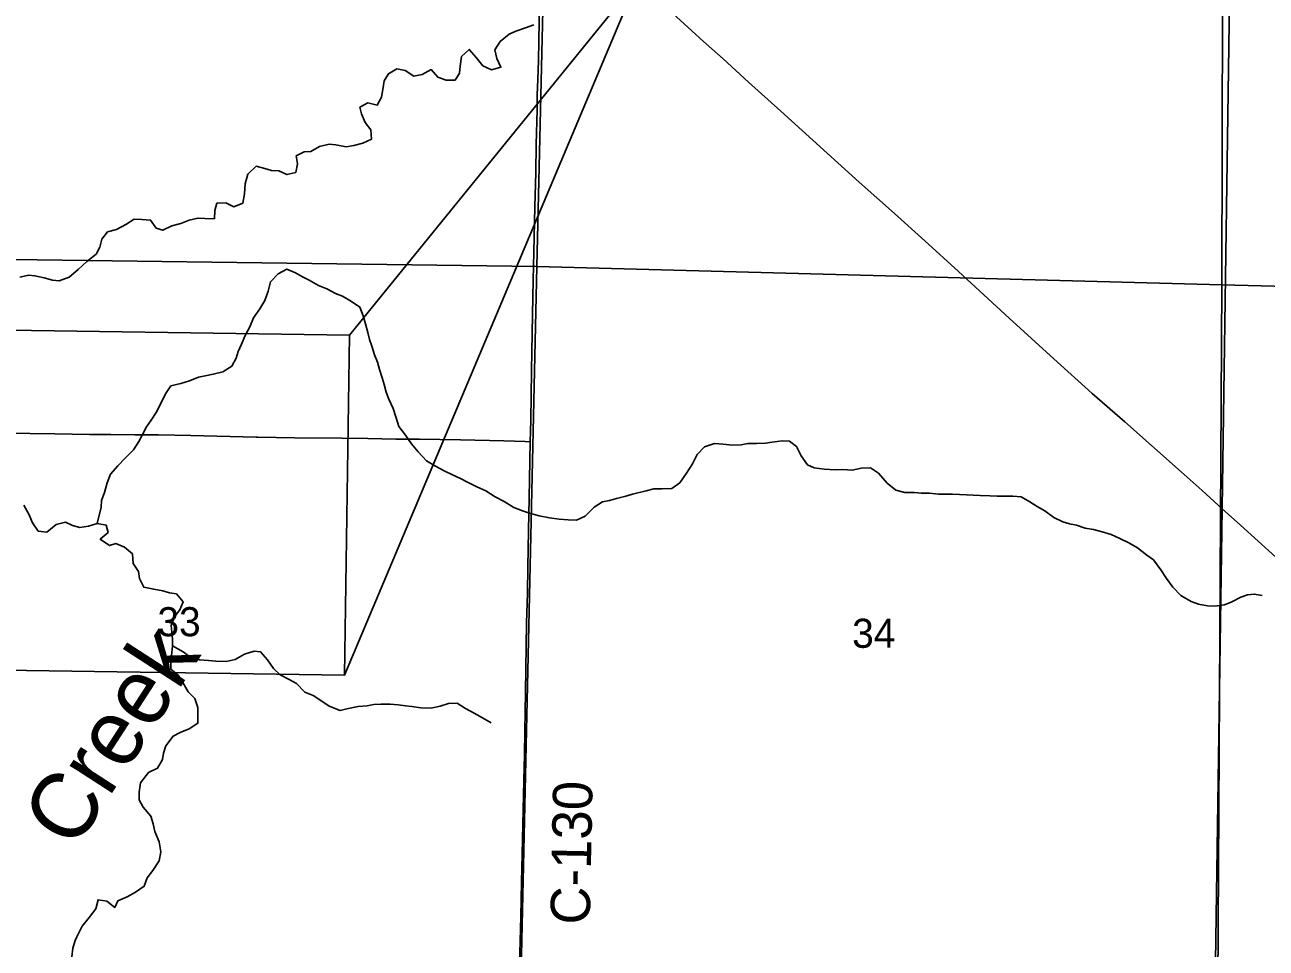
# Model space of a CAD drawing. Extents: x 0 to 34, y 0 to 22.
# Drawn here: x 5.278 to 7.066, y 15.686 to 17.017 of the extents above; entities that cross this region are included whole.
import ezdxf

# ---------------------------------------------------------------- set-up
doc = ezdxf.new("R2010")
doc.units = 0
for name, color, linetype in [('Default', 7, 'Continuous'), ('GM_X_City_Street', 7, 'Continuous'), ('GM_X_County_Road', 7, 'Continuous'), ('GM_X_Interchange_Ramps', 7, 'Continuous'), ('GM_X_Major_River_Text', 7, 'Continuous'), ('GM_X_Minor_River', 7, 'Continuous'), ('GM_X_Minor_River_Text', 7, 'Continuous'), ('GM_X_Rail_Line', 7, 'Continuous'), ('GM_X_Section', 7, 'Continuous'), ('GM_X_Unincorporated_Location', 7, 'Continuous'), ('SH_Border', 7, 'Continuous')]:
    doc.layers.add(name, color=color, linetype=linetype)

msp = doc.modelspace()

# ---------------------------------------------------------------- linework, layer by layer
at = {"layer": 'Default'}
for points in [[(7.0145, 17.1525), (7.0025, 16.32), (6.9926, 15.6339), (6.978, 14.6253), (6.9941, 14.625), (7.0745, 14.6221)], [(6.9926, 15.6339), (7.0025, 16.32), (7.0145, 17.1525)]]:
    msp.add_lwpolyline(points, dxfattribs=at)
at = {"layer": 'GM_X_City_Street'}
for points in [[(6.0058, 16.4159), (6.0064, 16.4467), (6.0076, 16.5181), (6.0089, 16.5992), (6.01, 16.6488), (6.0107, 16.6889), (6.0123, 16.7546), (6.0136, 16.8039), (6.0142, 16.8445), (6.0156, 16.8942), (6.0159, 16.9159), (6.0165, 16.9381), (6.0175, 16.9654), (6.018, 16.9934), (6.0187, 17.0215), (6.0201, 17.0708), (6.0212, 17.1147), (6.0221, 17.161), (6.0222, 17.1798), (6.0231, 17.1887), (6.0242, 17.1923), (6.026, 17.1948), (6.0285, 17.1978)], [(5.9907, 15.6551), (5.9907, 15.6636), (5.9909, 15.6791), (5.9921, 15.7319), (5.9933, 15.7816), (5.9942, 15.822), (5.9965, 15.9277), (5.9973, 15.9649), (5.9979, 15.9991), (5.9988, 16.0551), (6.0006, 16.1545), (6.0016, 16.198), (6.0023, 16.2353), (6.0032, 16.2881), (6.0042, 16.3347), (6.0058, 16.4159)]]:
    msp.add_lwpolyline(points, dxfattribs=at)
at = {"layer": 'GM_X_County_Road'}
for points in [[(5.8711, 17.3431), (5.8995, 17.3164), (5.9406, 17.2785), (5.9932, 17.23), (6.0161, 17.2091), (6.0285, 17.1978), (6.0617, 17.1677), (6.0897, 17.1423), (6.1497, 17.0881), (6.2052, 17.0383), (6.2497, 16.9979)], [(6.2497, 16.9979), (6.2512, 16.9965), (6.2836, 16.9675), (6.3204, 16.934), (6.3666, 16.8924), (6.4794, 16.7902), (6.5303, 16.7446), (6.5744, 16.7053), (6.6225, 16.6613), (6.6957, 16.594), (6.76, 16.5354), (6.8155, 16.4856), (6.8622, 16.4446), (6.9436, 16.3724), (6.9738, 16.3456), (7.0027, 16.3195)], [(7.0027, 16.3195), (7.0291, 16.2956), (7.0799, 16.2498), (7.1558, 16.1809), (7.1925, 16.1473), (7.2336, 16.1094), (7.2657, 16.08), (7.3452, 16.0057), (7.3814, 15.9718), (7.4226, 15.9339), (7.4544, 15.9041), (7.4861, 15.8744), (7.4979, 15.8643), (7.5018, 15.8606), (7.5256, 15.8381), (7.5518, 15.8138)]]:
    msp.add_lwpolyline(points, dxfattribs=at)
at = {"layer": 'GM_X_Interchange_Ramps'}
for points in [[(5.0014, 16.4326), (5.01, 16.4323), (5.0131, 16.4323), (5.0535, 16.4313), (5.0939, 16.4307), (5.1934, 16.4292), (5.2276, 16.4286), (5.2494, 16.4282), (5.3209, 16.4272), (5.3706, 16.4265), (5.4017, 16.4262), (5.4359, 16.4259), (5.4701, 16.4258), (5.5168, 16.4248), (5.6111, 16.4227)], [(5.6111, 16.4227), (5.6131, 16.4227), (5.666, 16.4217), (5.7344, 16.4209), (5.7717, 16.4204), (5.8121, 16.4198), (5.8463, 16.4195), (5.9054, 16.4186), (5.9676, 16.4171), (5.9986, 16.4161), (6.0058, 16.4159)]]:
    msp.add_lwpolyline(points, dxfattribs=at)
at = {"layer": 'GM_X_Rail_Line'}
msp.add_lwpolyline([(4.0103, 16.5951), (5.7456, 16.5696), (5.7384, 16.0796), (4.0031, 16.1052)], close=True, dxfattribs=at)
at = {"layer": 'GM_X_Section'}
for points in [[(6.0109, 17.0168), (5.9988, 17.0126), (5.9852, 17.0076), (5.9753, 17.0034), (5.9625, 16.9927), (5.9546, 16.9809), (5.9576, 16.9684), (5.9634, 16.9555), (5.9501, 16.9517), (5.9376, 16.9577), (5.9277, 16.9698), (5.9178, 16.9812), (5.9068, 16.9709), (5.905, 16.9572), (5.9039, 16.947), (5.8974, 16.9371), (5.8845, 16.9371), (5.8724, 16.9412), (5.8629, 16.9522), (5.85, 16.9449), (5.8379, 16.9426), (5.8257, 16.9509), (5.8135, 16.9535), (5.8014, 16.9463), (5.7954, 16.936), (5.7939, 16.9262), (5.7917, 16.9125)], [(5.7917, 16.9125), (5.7853, 16.9011), (5.772, 16.9041), (5.7603, 16.898), (5.7626, 16.8885), (5.7679, 16.876), (5.7759, 16.8654), (5.7771, 16.8521), (5.7646, 16.8464), (5.7517, 16.8426), (5.7407, 16.841), (5.7256, 16.844), (5.7161, 16.8447), (5.7024, 16.8413), (5.6899, 16.834), (5.6801, 16.8336), (5.6687, 16.8279), (5.6703, 16.8165), (5.668, 16.804), (5.6552, 16.8009), (5.6434, 16.8062), (5.6331, 16.8069), (5.6236, 16.8099), (5.6107, 16.8129), (5.599, 16.8015), (5.5953, 16.7874), (5.5942, 16.7734), (5.5916, 16.7597), (5.5787, 16.7544), (5.5673, 16.76), (5.5544, 16.7596), (5.5514, 16.7494), (5.5507, 16.7372), (5.537, 16.7376), (5.5268, 16.7383), (5.5143, 16.7352), (5.5022, 16.7302), (5.4893, 16.7272), (5.4764, 16.7207), (5.4669, 16.7237), (5.4589, 16.7354), (5.446, 16.7361), (5.4354, 16.7368), (5.4233, 16.7292), (5.4096, 16.722), (5.3968, 16.7185), (5.3884, 16.7079), (5.3858, 16.6961), (5.3802, 16.6862), (5.3669, 16.6755), (5.3545, 16.6641), (5.3416, 16.6531), (5.3272, 16.6477), (5.3173, 16.6488), (5.3056, 16.6522), (5.2923, 16.6552), (5.2828, 16.6559), (5.2703, 16.6532)], [(5.382, 16.2982), (5.3876, 16.3217), (5.3883, 16.3312), (5.3924, 16.343), (5.3965, 16.3567), (5.401, 16.3692), (5.4116, 16.381), (5.4222, 16.3924), (5.4343, 16.4042), (5.4418, 16.4164), (5.4471, 16.4266), (5.4531, 16.4376), (5.4596, 16.4472), (5.4671, 16.4582), (5.4735, 16.4711), (5.4803, 16.4848), (5.4882, 16.4966), (5.5026, 16.5), (5.5151, 16.5035), (5.528, 16.5088), (5.5375, 16.5108), (5.5492, 16.5131), (5.5629, 16.5165), (5.5761, 16.5249), (5.5821, 16.5363), (5.5848, 16.5462), (5.59, 16.5564), (5.5949, 16.569), (5.6017, 16.5815), (5.6073, 16.5944), (5.616, 16.6074), (5.6232, 16.6195), (5.6284, 16.6328), (5.6318, 16.6465), (5.6424, 16.6579), (5.6553, 16.6648), (5.6678, 16.6595), (5.6777, 16.6538), (5.6872, 16.6489), (5.7005, 16.641), (5.7126, 16.6361), (5.7252, 16.6297), (5.7354, 16.6256), (5.7484, 16.618), (5.7602, 16.6101), (5.7651, 16.5976), (5.7682, 16.5859), (5.7717, 16.5734), (5.7744, 16.5635), (5.7774, 16.5537), (5.7813, 16.5411), (5.7855, 16.5305), (5.7885, 16.5199), (5.7924, 16.5082), (5.7951, 16.4983), (5.7981, 16.4873), (5.802, 16.4775), (5.8085, 16.4639), (5.8123, 16.4517), (5.8165, 16.4381), (5.8261, 16.4252), (5.8348, 16.4131), (5.8444, 16.4014), (5.8562, 16.3882), (5.8695, 16.3806), (5.8816, 16.3738), (5.8949, 16.3678), (5.9052, 16.3629), (5.9154, 16.3576), (5.9287, 16.3512), (5.942, 16.3452), (5.9554, 16.3365), (5.9683, 16.3298), (5.982, 16.3211), (5.9945, 16.3166), (6.0048, 16.3132), (6.0188, 16.3094), (6.0336, 16.3061), (6.0473, 16.3042), (6.0602, 16.3035), (6.0723, 16.3028), (6.0848, 16.3089), (6.098, 16.3218), (6.1098, 16.3295), (6.12, 16.3314), (6.1299, 16.3341), (6.1435, 16.3375), (6.153, 16.3406), (6.1727, 16.3452), (6.1837, 16.3479), (6.1958, 16.348), (6.2095, 16.3484), (6.2212, 16.3568), (6.231, 16.3705), (6.2393, 16.3841), (6.2461, 16.3974), (6.2567, 16.4088), (6.2711, 16.4134), (6.2836, 16.4123), (6.2965, 16.4109), (6.3097, 16.4117)], [(6.3097, 16.4117), (6.3192, 16.4132), (6.3317, 16.4133), (6.3446, 16.4141), (6.3541, 16.4152), (6.3689, 16.4172), (6.3791, 16.4168), (6.3894, 16.4093), (6.3959, 16.3957), (6.4051, 16.3828), (6.4149, 16.3783), (6.4294, 16.3764), (6.4449, 16.3753), (6.4559, 16.3758), (6.4696, 16.375), (6.4828, 16.3777), (6.4957, 16.3785), (6.5075, 16.3706), (6.5201, 16.3562), (6.5326, 16.3464), (6.5456, 16.343), (6.5592, 16.3427), (6.5687, 16.342), (6.5808, 16.3417), (6.5941, 16.3406), (6.6142, 16.3406), (6.6241, 16.3399), (6.6537, 16.3385), (6.6677, 16.3378), (6.6783, 16.3374), (6.7011, 16.3375), (6.7132, 16.3368), (6.7254, 16.3292), (6.736, 16.3224), (6.7471, 16.3164), (6.76, 16.307), (6.7729, 16.3006), (6.7824, 16.2976), (6.7927, 16.2957), (6.8052, 16.2916), (6.8173, 16.2897), (6.8299, 16.2863), (6.8424, 16.2822), (6.8549, 16.2766), (6.8682, 16.2702), (6.8808, 16.263), (6.8941, 16.2524), (6.9036, 16.2456), (6.9143, 16.2316), (6.9223, 16.2191), (6.9314, 16.2066), (6.9429, 16.1945), (6.9581, 16.1859), (6.9683, 16.1817), (6.9812, 16.1795), (6.9919, 16.1792), (7.0059, 16.1807), (7.0165, 16.1853), (7.0294, 16.1918), (7.0388, 16.1952), (7.0487, 16.1964), (7.0601, 16.1942)], [(5.276, 16.3244), (5.284, 16.3108), (5.2886, 16.299), (5.297, 16.2869)], [(5.297, 16.2869), (5.3095, 16.2855), (5.3228, 16.2965), (5.3364, 16.3), (5.3463, 16.2954), (5.3569, 16.2924), (5.3694, 16.2944), (5.382, 16.2982), (5.3949, 16.2956), (5.3976, 16.2854), (5.3862, 16.2755), (5.3995, 16.2664), (5.409, 16.2691), (5.4211, 16.2642), (5.4329, 16.2544), (5.4337, 16.2407), (5.4414, 16.229), (5.4429, 16.2191), (5.449, 16.2063), (5.4635, 16.2033), (5.4764, 16.2011), (5.4862, 16.1984), (5.4961, 16.1966), (5.5056, 16.1852), (5.5008, 16.1735), (5.4932, 16.1636), (5.4887, 16.151), (5.4895, 16.1416), (5.4903, 16.1317), (5.4903, 16.1218), (5.4896, 16.1123), (5.4881, 16.0983), (5.4878, 16.0881), (5.4984, 16.0798), (5.5053, 16.0692), (5.5129, 16.0555), (5.5225, 16.0461), (5.5267, 16.0332), (5.5271, 16.0211), (5.5271, 16.0104), (5.5146, 16.0024), (5.5014, 15.9971), (5.4912, 15.9917), (5.4806, 15.9777), (5.4772, 15.9674), (5.4761, 15.9579), (5.469, 15.9458), (5.4557, 15.9393), (5.4444, 15.9245), (5.4425, 15.9108), (5.4426, 15.8998), (5.4483, 15.8896), (5.459, 15.8763), (5.4624, 15.8653), (5.4651, 15.8544), (5.4712, 15.8392), (5.4736, 15.8252), (5.471, 15.8119), (5.4619, 15.7982), (5.454, 15.7876), (5.4498, 15.7754), (5.437, 15.7667), (5.4249, 15.7602), (5.4116, 15.7544), (5.4071, 15.7449), (5.3957, 15.754), (5.3832, 15.7559), (5.3798, 15.7429), (5.3703, 15.7304), (5.3602, 15.7178), (5.3526, 15.7027), (5.35, 15.6973)], [(5.4903, 16.1218), (5.5059, 16.1132), (5.5154, 16.106), (5.5291, 16.1015), (5.5424, 16.1008), (5.5526, 16.0997), (5.5678, 16.0993), (5.5807, 16.102), (5.5939, 16.11), (5.6079, 16.1143), (5.6174, 16.1132), (5.6273, 16.1018), (5.6361, 16.0893), (5.6456, 16.0803), (5.6585, 16.0735), (5.6692, 16.0674), (5.681, 16.0553), (5.6931, 16.0504), (5.7057, 16.0421), (5.7163, 16.035), (5.7319, 16.0286), (5.7414, 16.0309), (5.7581, 16.0344), (5.771, 16.0355), (5.7804, 16.0371), (5.7903, 16.0379), (5.8039, 16.0379), (5.8153, 16.0368), (5.826, 16.0353), (5.8354, 16.0342), (5.8483, 16.0324), (5.8628, 16.032), (5.876, 16.0351), (5.8882, 16.0386), (5.9003, 16.0394), (5.9125, 16.0315), (5.925, 16.0247), (5.9368, 16.0179), (5.9497, 16.0111)], [(5.3455, 15.6738), (5.3466, 15.6863), (5.35, 15.6973)]]:
    msp.add_lwpolyline(points, dxfattribs=at)
at = {"layer": 'GM_X_Unincorporated_Location'}
for points in [[(6.0388, 17.6742), (6.0154, 16.6684), (5.0069, 16.682), (5.0326, 17.6924)], [(7.0045, 17.6571), (7.0019, 16.6421), (6.0154, 16.6684), (6.0388, 17.6742)], [(7.0045, 17.6571), (8.0227, 17.628), (8.0236, 17.3548), (8.0033, 16.6164), (7.0019, 16.6421)], [(6.0154, 16.6684), (5.9927, 15.6543), (4.9903, 15.675), (5.0069, 16.682)], [(7.0019, 16.6421), (6.9963, 15.6339), (5.9927, 15.6543), (6.0154, 16.6684)], [(8.0033, 16.6164), (7.9948, 16.3527), (7.9737, 15.6015), (6.9963, 15.6339), (7.0019, 16.6421)]]:
    msp.add_lwpolyline(points, close=True, dxfattribs=at)
at = {"layer": 'SH_Border'}
for points in [[(6.1594, 17.0794), (5.7456, 16.5696), (5.7384, 16.0796)], [(4.0031, 16.1052), (5.7384, 16.0796), (5.7456, 16.5696), (4.0103, 16.5951)]]:
    msp.add_lwpolyline(points, close=True, dxfattribs=at)

# ---------------------------------------------------------------- texts
at = {"layer": 'GM_X_Major_River_Text'}
for s, p in [('33', (5.4687, 16.1357)), ('34', (6.4695, 16.119))]:
    msp.add_text(s, height=0.04186, rotation=0, dxfattribs=at).set_placement(p)
at = {"layer": 'GM_X_Minor_River'}
msp.add_text('Creek', height=0.09471, rotation=57.0829, dxfattribs=at).set_placement((5.3489, 15.8255))
at = {"layer": 'GM_X_Minor_River_Text'}
msp.add_text('C-130', height=0.05682, rotation=88.8986, dxfattribs=at).set_placement((6.0916, 15.7198))

doc.saveas('drawing.dxf')
